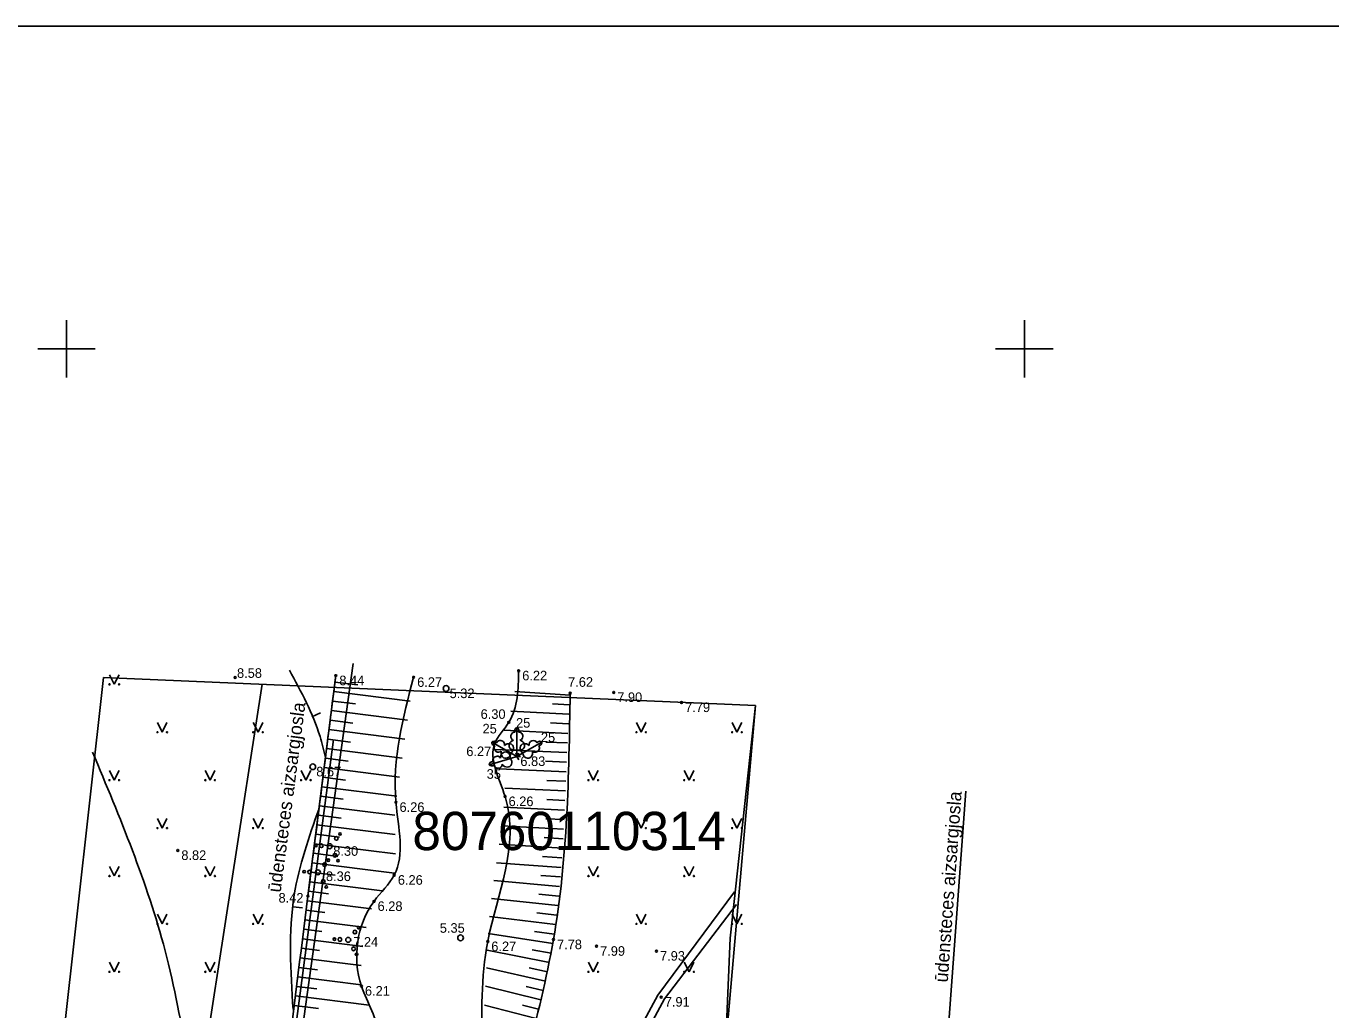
# Model space of a CAD drawing. Extents: x 496127 to 496334, y 303823 to 303967.
# Drawn here: x 496197.9 to 496266, y 303915.5 to 303966.8 of the extents above; entities that cross this region are included whole.
import ezdxf

# ---------------------------------------------------------------- set-up
doc = ezdxf.new("R2010")
doc.units = 0
for name, color, linetype in [('APGR_AIZS_####_####_#', 7, 'Continuous'), ('APGR_AIZS_####_TKST_#', 7, 'Continuous'), ('BUVE_ELEM_####_####_#', 7, 'Continuous'), ('CELI_TAKA_####_####_#', 7, 'Continuous'), ('GEOD_ELEM_####_####_#', 7, 'Continuous'), ('HIDG_AATZ_####_TKST_#', 7, 'Continuous'), ('HIDG_ELEM_####_####_#', 7, 'Continuous'), ('HIDG_PLIN_####_####_#', 7, 'Continuous'), ('Level 24', 7, 'Continuous'), ('Level 59', 7, 'Continuous'), ('RAMI_PLAN_####_TKST_#', 7, 'Continuous'), ('RAMI_UZMR_####_####_#', 7, 'Continuous'), ('RELJ_AATZ_####_TKST_#', 7, 'Continuous'), ('RELJ_ELEM_####_####_#', 7, 'Continuous'), ('RELJ_HORZ_PAMT_####_#', 7, 'Continuous'), ('RELJ_NOGA_####_####_#', 7, 'Continuous'), ('SAKT_VADP_KABE_####_#', 7, 'Continuous'), ('TERT_DIAM_####_TKST_#', 7, 'Continuous'), ('TERT_ELEM_####_####_#', 7, 'Continuous')]:
    doc.layers.add(name, color=color, linetype=linetype)

msp = doc.modelspace()

# ---------------------------------------------------------------- linework, layer by layer
at = {"layer": 'APGR_AIZS_####_####_#'}
for points in [[(496206.5, 303871.056), (496206.335, 303871.77), (496213.935, 303929.615)], [(496246.945, 303926.926), (496242.62, 303868.109)]]:
    msp.add_lwpolyline(points, dxfattribs=at)
at = {"layer": 'BUVE_ELEM_####_####_#'}
msp.add_circle((496212.857, 303928.197), 0.148, dxfattribs=at)
at = {"layer": 'CELI_TAKA_####_####_#'}
for points in [[(496219.605, 303897.231), (496219.853, 303897.223), (496222.633, 303901.604), (496224.89, 303905.204), (496230.869, 303916.278), (496234.875, 303921.675)], [(496219.581, 303896.831), (496220.069, 303896.815), (496225.236, 303905.002), (496231.221, 303916.088), (496234.977, 303921.017)]]:
    msp.add_lwpolyline(points, dxfattribs=at)
at = {"layer": 'GEOD_ELEM_####_####_#'}
for p, q in [((496200, 303951.5), (496200, 303950)), ((496250, 303951.5), (496250, 303950)), ((496198.5, 303950), (496200, 303950)), ((496200, 303950), (496200, 303948.5)), ((496200, 303950), (496201.5, 303950)), ((496248.5, 303950), (496250, 303950)), ((496250, 303950), (496250, 303948.5)), ((496250, 303950), (496251.5, 303950))]:
    msp.add_line(p, q, dxfattribs=at)
at = {"layer": 'HIDG_ELEM_####_####_#'}
for centre in [(496219.814, 303932.281), (496220.575, 303919.275)]:
    msp.add_circle(centre, 0.15, dxfattribs=at)
at = {"layer": 'HIDG_PLIN_####_####_#'}
for points in [[(496221.71, 303913.418), (496221.991, 303919.078), (496222.893, 303926.646), (496222.355, 303929.415), (496223.088, 303930.517), (496223.605, 303933.206)], [(496215.703, 303911.989), (496216.304, 303914.216), (496215.397, 303916.759), (496216.055, 303921.177), (496217.113, 303922.543), (496217.201, 303926.345), (496218.123, 303932.867)]]:
    msp.add_spline(points, degree=3, dxfattribs=at)
at = {"layer": 'Level 24'}
for points in [[(496207.017, 303876.387), (496214.972, 303933.586)], [(496235.974, 303931.399), (496234.652, 303919.252)], [(496234.652, 303919.252), (496232.313, 303864.302)]]:
    msp.add_lwpolyline(points, dxfattribs=at)
at = {"layer": 'RAMI_PLAN_####_TKST_#'}
msp.add_line((496334.105, 303966.843), (496138.105, 303966.843), dxfattribs=at)
at = {"layer": 'RAMI_UZMR_####_####_#'}
for p, q in [((496201.94, 303932.86), (496199.386, 303909.951)), ((496235.974, 303931.399), (496201.94, 303932.86)), ((496234.504, 303914.713), (496235.974, 303931.399))]:
    msp.add_line(p, q, dxfattribs=at)
at = {"layer": 'RELJ_ELEM_####_####_#'}
for centre in [(496223.605, 303933.206), (496208.804, 303932.854), (496214.059, 303932.953), (496218.123, 303932.867), (496226.293, 303932.035), (496228.566, 303932.079), (496232.109, 303931.552), (496223.088, 303930.517), (496222.355, 303929.415), (496217.201, 303926.345), (496222.893, 303926.646), (496205.812, 303923.836), (496217.113, 303922.543), (496212.609, 303921.456), (496216.055, 303921.177), (496221.991, 303919.078), (496225.421, 303919.181), (496227.67, 303918.837), (496230.797, 303918.58), (496215.397, 303916.759), (496231.045, 303916.183)]:
    msp.add_circle(centre, 0.05, dxfattribs=at)
at = {"layer": 'RELJ_HORZ_PAMT_####_#'}
for p, q in [((496213.27, 303931.019), (496212.814, 303930.812)), ((496212.318, 303920.838), (496211.82, 303920.884))]:
    msp.add_line(p, q, dxfattribs=at)
for points in [[(496211.636, 303933.236), (496213.237, 303929.782), (496213.522, 303928.69)], [(496206.353, 303912.842), (496205.148, 303918.603), (496201.364, 303928.964)], [(496213.185, 303926.024), (496211.895, 303921.52), (496211.832, 303915.527)]]:
    msp.add_spline(points, degree=3, dxfattribs=at)
at = {"layer": 'RELJ_NOGA_####_####_#'}
for p, q in [((496212.609, 303921.456), (496214.059, 303932.953)), ((496214.017, 303932.616), (496215.216, 303932.465)), ((496213.954, 303932.12), (496217.946, 303931.617)), ((496226.286, 303931.935), (496223.398, 303932.128)), ((496213.891, 303931.624), (496215.087, 303931.474)), ((496226.255, 303931.436), (496225.368, 303931.49)), ((496213.766, 303930.632), (496214.957, 303930.482)), ((496213.829, 303931.128), (496217.806, 303930.627)), ((496226.225, 303930.937), (496223.201, 303931.104)), ((496226.198, 303930.437), (496225.27, 303930.486)), ((496213.704, 303930.136), (496217.666, 303929.637)), ((496226.173, 303929.938), (496222.848, 303930.103)), ((496213.579, 303929.144), (496217.526, 303928.646)), ((496213.641, 303929.64), (496214.828, 303929.49)), ((496226.127, 303928.939), (496222.339, 303929.108)), ((496226.149, 303929.439), (496225.032, 303929.49)), ((496213.516, 303928.648), (496214.698, 303928.499)), ((496226.105, 303928.44), (496225.001, 303928.486)), ((496213.454, 303928.152), (496217.386, 303927.656)), ((496226.084, 303927.94), (496222.586, 303928.088)), ((496213.329, 303927.16), (496217.246, 303926.665)), ((496213.391, 303927.656), (496214.569, 303927.507)), ((496226.042, 303926.941), (496222.879, 303927.077)), ((496226.063, 303927.441), (496225.072, 303927.482)), ((496213.266, 303926.664), (496214.44, 303926.515)), ((496226.02, 303926.441), (496225.08, 303926.483)), ((496213.203, 303926.168), (496217.144, 303925.67)), ((496225.997, 303925.942), (496222.836, 303926.088)), ((496213.078, 303925.175), (496217.151, 303924.661)), ((496213.141, 303925.671), (496214.34, 303925.52)), ((496225.948, 303924.943), (496222.719, 303925.116)), ((496225.974, 303925.443), (496225.015, 303925.489)), ((496213.016, 303924.679), (496214.261, 303924.522)), ((496225.921, 303924.444), (496224.941, 303924.501)), ((496212.891, 303923.687), (496214.174, 303923.525)), ((496212.953, 303924.183), (496217.178, 303923.65)), ((496225.891, 303923.945), (496222.587, 303924.152)), ((496212.828, 303923.191), (496217.127, 303922.649)), ((496225.823, 303922.947), (496222.448, 303923.192)), ((496225.858, 303923.446), (496224.856, 303923.515)), ((496212.765, 303922.695), (496214.019, 303922.537)), ((496225.784, 303922.449), (496224.763, 303922.531)), ((496212.64, 303921.703), (496213.677, 303921.572)), ((496212.703, 303922.199), (496216.483, 303921.722)), ((496225.742, 303921.95), (496222.315, 303922.256)), ((496212.577, 303921.207), (496215.917, 303920.785)), ((496225.644, 303920.955), (496222.193, 303921.325)), ((496225.695, 303921.453), (496224.662, 303921.553)), ((496212.515, 303920.711), (496213.492, 303920.587)), ((496225.528, 303919.962), (496222.09, 303920.395)), ((496225.589, 303920.458), (496224.554, 303920.58)), ((496212.389, 303919.719), (496213.337, 303919.599)), ((496212.452, 303920.215), (496215.648, 303919.811)), ((496225.462, 303919.466), (496224.438, 303919.609)), ((496212.327, 303919.223), (496215.471, 303918.825)), ((496225.389, 303918.972), (496222.016, 303919.504)), ((496212.201, 303918.231), (496215.384, 303917.828)), ((496212.264, 303918.727), (496213.21, 303918.607)), ((496225.212, 303917.988), (496221.969, 303918.629)), ((496225.306, 303918.479), (496224.311, 303918.654)), ((496212.138, 303917.734), (496213.11, 303917.612)), ((496225.001, 303917.01), (496221.923, 303917.716)), ((496225.11, 303917.498), (496224.161, 303917.704)), ((496212.076, 303917.238), (496215.393, 303916.819)), ((496211.95, 303916.246), (496215.801, 303915.759)), ((496212.013, 303916.742), (496213.064, 303916.609)), ((496224.767, 303916.038), (496221.876, 303916.756)), ((496224.886, 303916.524), (496223.99, 303916.741)), ((496211.887, 303915.75), (496213.156, 303915.59)), ((496224.522, 303915.069), (496221.826, 303915.752)), ((496224.645, 303915.553), (496223.807, 303915.766))]:
    msp.add_line(p, q, dxfattribs=at)
for points in [[(496211.448, 303912.278), (496212.609, 303921.456), (496214.059, 303932.953)], [(496224.046, 303913.126), (496225.421, 303919.181), (496226.293, 303932.035)]]:
    msp.add_spline(points, degree=3, dxfattribs=at)
at = {"layer": 'SAKT_VADP_KABE_####_#'}
msp.add_lwpolyline([(496210.224, 303932.504), (496206.983, 303911.574), (496201.442, 303876.244), (496202.133, 303859.823)], dxfattribs=at)
at = {"layer": 'TERT_ELEM_####_####_#'}
for p, q in [((496202.25, 303933), (496202.5, 303932.5)), ((496202.5, 303932.5), (496202.75, 303933)), ((496204.75, 303930.5), (496205, 303930)), ((496205, 303930), (496205.25, 303930.5)), ((496209.75, 303930.5), (496210, 303930)), ((496210, 303930), (496210.25, 303930.5)), ((496229.75, 303930.5), (496230, 303930)), ((496230, 303930), (496230.25, 303930.5)), ((496234.75, 303930.5), (496235, 303930)), ((496235, 303930), (496235.25, 303930.5)), ((496223.176, 303928.638), (496223.508, 303928.738)), ((496223.207, 303928.911), (496223.508, 303928.738)), ((496223.508, 303928.738), (496223.45, 303928.93)), ((496223.508, 303929.085), (496223.508, 303928.738)), ((496223.508, 303928.738), (496223.608, 303928.911)), ((496223.809, 303928.911), (496223.508, 303928.738)), ((496223.508, 303928.738), (496223.708, 303928.738)), ((496223.508, 303928.738), (496223.608, 303928.565)), ((496202.25, 303928), (496202.5, 303927.5)), ((496202.5, 303927.5), (496202.75, 303928)), ((496207.25, 303928), (496207.5, 303927.5)), ((496207.5, 303927.5), (496207.75, 303928)), ((496212.25, 303928), (496212.5, 303927.5)), ((496212.5, 303927.5), (496212.75, 303928)), ((496227.25, 303928), (496227.5, 303927.5)), ((496227.5, 303927.5), (496227.75, 303928)), ((496232.25, 303928), (496232.5, 303927.5)), ((496232.5, 303927.5), (496232.75, 303928)), ((496204.75, 303925.5), (496205, 303925)), ((496205, 303925), (496205.25, 303925.5)), ((496209.75, 303925.5), (496210, 303925)), ((496210, 303925), (496210.25, 303925.5)), ((496229.75, 303925.5), (496230, 303925)), ((496230, 303925), (496230.25, 303925.5)), ((496234.75, 303925.5), (496235, 303925)), ((496235, 303925), (496235.25, 303925.5)), ((496202.25, 303923), (496202.5, 303922.5)), ((496202.5, 303922.5), (496202.75, 303923)), ((496207.25, 303923), (496207.5, 303922.5)), ((496207.5, 303922.5), (496207.75, 303923)), ((496227.25, 303923), (496227.5, 303922.5)), ((496227.5, 303922.5), (496227.75, 303923)), ((496232.25, 303923), (496232.5, 303922.5)), ((496232.5, 303922.5), (496232.75, 303923)), ((496204.75, 303920.5), (496205, 303920)), ((496205, 303920), (496205.25, 303920.5)), ((496209.75, 303920.5), (496210, 303920)), ((496210, 303920), (496210.25, 303920.5)), ((496229.75, 303920.5), (496230, 303920)), ((496230, 303920), (496230.25, 303920.5)), ((496234.75, 303920.5), (496235, 303920)), ((496235, 303920), (496235.25, 303920.5)), ((496202.25, 303918), (496202.5, 303917.5)), ((496202.5, 303917.5), (496202.75, 303918)), ((496207.25, 303918), (496207.5, 303917.5)), ((496207.5, 303917.5), (496207.75, 303918)), ((496227.25, 303918), (496227.5, 303917.5)), ((496227.5, 303917.5), (496227.75, 303918)), ((496232.25, 303918), (496232.5, 303917.5)), ((496232.5, 303917.5), (496232.75, 303918))]:
    msp.add_line(p, q, dxfattribs=at)
for points in [[(496223.508, 303930.238), (496223.508, 303929.085)], [(496223.598, 303930.006), (496223.597, 303930.007)], [(496222.209, 303929.488), (496223.207, 303928.911)], [(496222.455, 303929.449), (496222.454, 303929.449)], [(496224.807, 303929.488), (496223.809, 303928.911)], [(496224.651, 303929.294), (496224.651, 303929.296)], [(496222.071, 303928.307), (496223.176, 303928.638)], [(496222.268, 303928.459), (496222.268, 303928.458)]]:
    msp.add_lwpolyline(points, dxfattribs=at)
for centre, radius in [((496202.25, 303932.5), 0.028), ((496202.75, 303932.5), 0.0263), ((496204.75, 303930), 0.028), ((496205.25, 303930), 0.0263), ((496209.75, 303930), 0.028), ((496210.25, 303930), 0.0263), ((496229.75, 303930), 0.028), ((496230.25, 303930), 0.0263), ((496234.75, 303930), 0.028), ((496235.25, 303930), 0.0263), ((496202.25, 303927.5), 0.028), ((496202.75, 303927.5), 0.0263), ((496207.25, 303927.5), 0.028), ((496207.75, 303927.5), 0.0263), ((496212.25, 303927.5), 0.028), ((496212.75, 303927.5), 0.0263), ((496227.25, 303927.5), 0.028), ((496227.75, 303927.5), 0.0263), ((496232.25, 303927.5), 0.028), ((496232.75, 303927.5), 0.0263), ((496204.75, 303925), 0.028), ((496205.25, 303925), 0.0263), ((496209.75, 303925), 0.028), ((496210.25, 303925), 0.0263), ((496229.75, 303925), 0.028), ((496230.25, 303925), 0.0263), ((496234.75, 303925), 0.028), ((496235.25, 303925), 0.0263), ((496214.089, 303924.461), 0.096), ((496214.285, 303924.692), 0.064), ((496213.023, 303924.087), 0.064), ((496213.307, 303924.074), 0.096), ((496213.741, 303924.053), 0.128), ((496214.017, 303923.586), 0.096), ((496213.475, 303923.096), 0.096), ((496213.671, 303923.327), 0.064), ((496214.175, 303923.297), 0.064), ((496202.25, 303922.5), 0.028), ((496202.75, 303922.5), 0.0263), ((496207.25, 303922.5), 0.028), ((496207.75, 303922.5), 0.0263), ((496212.409, 303922.722), 0.064), ((496212.693, 303922.709), 0.096), ((496213.127, 303922.688), 0.128), ((496213.403, 303922.221), 0.096), ((496227.25, 303922.5), 0.028), ((496227.75, 303922.5), 0.0263), ((496232.25, 303922.5), 0.028), ((496232.75, 303922.5), 0.0263), ((496213.561, 303921.932), 0.064), ((496204.75, 303920), 0.028), ((496205.25, 303920), 0.0263), ((496209.75, 303920), 0.028), ((496210.25, 303920), 0.0263), ((496215.057, 303919.577), 0.096), ((496215.057, 303919.573), 0.096), ((496215.253, 303919.808), 0.064), ((496215.253, 303919.804), 0.064), ((496229.75, 303920), 0.028), ((496230.25, 303920), 0.0263), ((496234.75, 303920), 0.028), ((496235.25, 303920), 0.0263), ((496213.991, 303919.203), 0.064), ((496213.991, 303919.199), 0.064), ((496214.275, 303919.19), 0.096), ((496214.275, 303919.186), 0.096), ((496214.709, 303919.169), 0.128), ((496214.709, 303919.165), 0.128), ((496214.985, 303918.702), 0.096), ((496214.985, 303918.698), 0.096), ((496215.143, 303918.413), 0.064), ((496215.143, 303918.409), 0.064), ((496202.25, 303917.5), 0.028), ((496202.75, 303917.5), 0.0263), ((496207.25, 303917.5), 0.028), ((496207.75, 303917.5), 0.0263), ((496227.25, 303917.5), 0.028), ((496227.75, 303917.5), 0.0263), ((496232.25, 303917.5), 0.028), ((496232.75, 303917.5), 0.0263)]:
    msp.add_circle(centre, radius, dxfattribs=at)
for centre, major_axis, ratio, start_param, end_param in [((496223.38, 303929.793), (-0.039, -0.212), 0.861323, 3.141593, 6.283185), ((496223.508, 303930.088), (0, -0.15), 0.707107, 3.14537, 5.287485), ((496223.508, 303930.088), (0, -0.15), 0.707107, 0.995701, 3.137816), ((496223.636, 303929.793), (0.039, -0.212), 0.861323, 0, 3.141593), ((496222.339, 303929.413), (0.13, -0.075), 0.707107, 3.14537, 5.287485), ((496222.339, 303929.413), (0.13, -0.075), 0.707107, 0.995701, 3.137816), ((496222.53, 303929.154), (0.165, -0.14), 0.861323, 3.141593, 6.283185), ((496222.658, 303929.377), (0.203, -0.073), 0.861323, 0, 3.141593), ((496223.039, 303929.112), (-0.236, -0.218), 0.814445, 1.531171, 4.712389), ((496223.418, 303929.331), (0.307, 0.095), 0.814445, 1.570796, 4.752015), ((496223.598, 303929.331), (-0.307, 0.095), 0.814445, 1.531171, 4.712389), ((496223.977, 303929.112), (0.236, -0.218), 0.814445, 1.570796, 4.752015), ((496224.358, 303929.377), (-0.203, -0.073), 0.861323, 3.141593, 6.283185), ((496224.486, 303929.154), (-0.165, -0.14), 0.861323, 0, 3.141593), ((496224.677, 303929.413), (-0.13, -0.075), 0.707107, 3.14537, 5.287485), ((496224.677, 303929.413), (-0.13, -0.075), 0.707107, 0.995701, 3.137816), ((496222.215, 303928.349), (0.144, 0.043), 0.707107, 0.995701, 3.137816), ((496222.46, 303928.557), (0.192, 0.098), 0.861323, 0, 3.141593), ((496222.914, 303928.653), (-0.003, -0.321), 0.814445, 1.531171, 4.712389), ((496222.95, 303928.957), (0.071, 0.313), 0.814445, 1.570796, 4.752015), ((496222.966, 303928.482), (-0.179, 0.267), 0.814445, 1.570796, 4.752015), ((496224.066, 303928.957), (-0.071, 0.313), 0.814445, 1.531171, 4.712389), ((496222.215, 303928.35), (0.144, 0.043), 0.707107, 3.14537, 5.287485), ((496222.534, 303928.312), (0.215, 0.024), 0.861323, 3.141593, 6.283185)]:
    msp.add_ellipse(centre, major_axis=major_axis, ratio=ratio, start_param=start_param, end_param=end_param, dxfattribs=at)

# ---------------------------------------------------------------- texts
at = {"layer": 'APGR_AIZS_####_TKST_#'}
for rotation, p in [(82.5152, (496211.183, 303921.613)), (85.7948, (496245.999, 303916.928))]:
    msp.add_text('ūdensteces aizsargjosla', height=0.7, rotation=rotation, dxfattribs=at).set_placement(p)
at = {"layer": 'HIDG_AATZ_####_TKST_#'}
for s, p in [(' 5.32', (496219.814, 303931.781)), (' 5.35', (496219.303, 303919.538))]:
    msp.add_text(s, height=0.5, dxfattribs=at).set_placement(p)
at = {"layer": 'Level 59'}
msp.add_text('80760110314', height=2, dxfattribs=at).set_placement((496218.058, 303923.849))
at = {"layer": 'RELJ_AATZ_####_TKST_#'}
for s, p in [(' 8.58', (496208.719, 303932.838)), (' 6.22', (496223.605, 303932.706)), (' 8.44', (496214.059, 303932.453)), (' 6.27', (496218.123, 303932.367)), (' 7.62', (496226.001, 303932.372)), (' 7.90', (496228.566, 303931.579)), (' 6.30', (496221.434, 303930.698)), (' 7.79', (496232.109, 303931.052)), (' 6.27', (496220.687, 303928.755)), (' 6.83', (496223.508, 303928.238)), (' 8.67', (496212.857, 303927.697)), (' 6.26', (496222.893, 303926.146)), (' 6.26', (496217.201, 303925.845)), (' 8.82', (496205.812, 303923.336)), (' 8.30', (496213.741, 303923.553)), (' 8.36', (496213.361, 303922.236)), (' 6.26', (496217.113, 303922.043)), (' 8.42', (496210.886, 303921.111)), (' 6.28', (496216.055, 303920.677)), (' 7.24', (496214.785, 303918.813)), (' 6.27', (496221.991, 303918.578)), (' 7.78', (496225.421, 303918.681)), (' 7.99', (496227.67, 303918.337)), (' 7.93', (496230.797, 303918.08)), (' 6.21', (496215.397, 303916.259)), (' 7.91', (496231.045, 303915.683))]:
    msp.add_text(s, height=0.5, dxfattribs=at).set_placement(p)
at = {"layer": 'TERT_DIAM_####_TKST_#'}
for s, p in [(' 25', (496223.283, 303930.238)), (' 25', (496221.534, 303929.938)), (' 25', (496224.582, 303929.488)), ('35', (496221.935, 303927.572))]:
    msp.add_text(s, height=0.5, dxfattribs=at).set_placement(p)

doc.saveas('drawing.dxf')
